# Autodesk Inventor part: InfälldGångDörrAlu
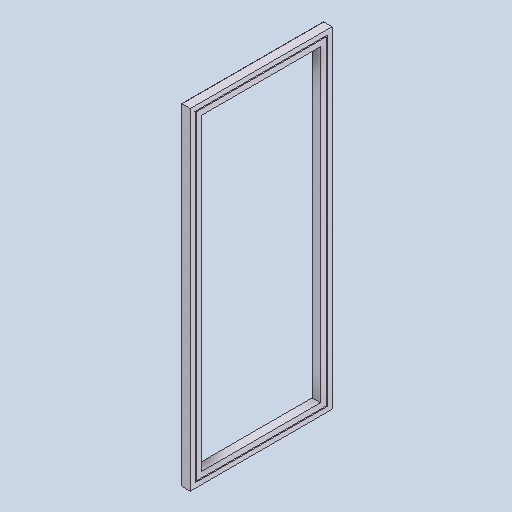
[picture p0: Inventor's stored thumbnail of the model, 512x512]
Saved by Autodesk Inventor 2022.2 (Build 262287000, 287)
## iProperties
Created: 2022-02
Part Number: InfälldGångDörrAlu
Material: Aluminum 6061, Welded
Document SubType Name: Modeling
Designer: cl
Density: 2.7 g/cm^3
Appearance: Weld - Aluminum
Author: cl
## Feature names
1. Extrusion1
2. Sweep1
## Parameters: BladBredd = 987.5 mm, Fönsterhöjd = 862 mm, Blad2 = 1012.5 mm, Blad3 = 0, Blad4 = 0, Blad5 = 1012.5 mm, Blad6 = 2025 mm, MGJ12Djup = 0, MGJ12Bredd = 0, MGJ2Djup = 0, MGJ2Bredd = 5012.5 mm, MGJ56Djup = 0, MGJ56Bredd = 0, MGJ23Djup = 48 mm, MGJ45Djup = 48 mm, GarageRegel5 = 0, GarageRegel6 = 0, Styrrulle2Djup = 0, FönsterhöjdStyrning = 862 mm, FönsterKarm = 54 mm, AndraGlasraden = 0, BrösthöjdStyrning2 = 0.0001 mm, InfälldGångDörr = 0, Infälldstyr = 845.83333 mm, d0 = 817.5 mm, d1 = 1991 mm, d4 = 6 mm, d5 = 41 mm, d6 = 52 mm, d7 = 0, d16 = 0, d17 = 0, d21 = 5 mm, d22 = 25 mm, d23 = 12 mm, d25 = 5 mm, d27 = 45 mm, d28 = 4 mm
